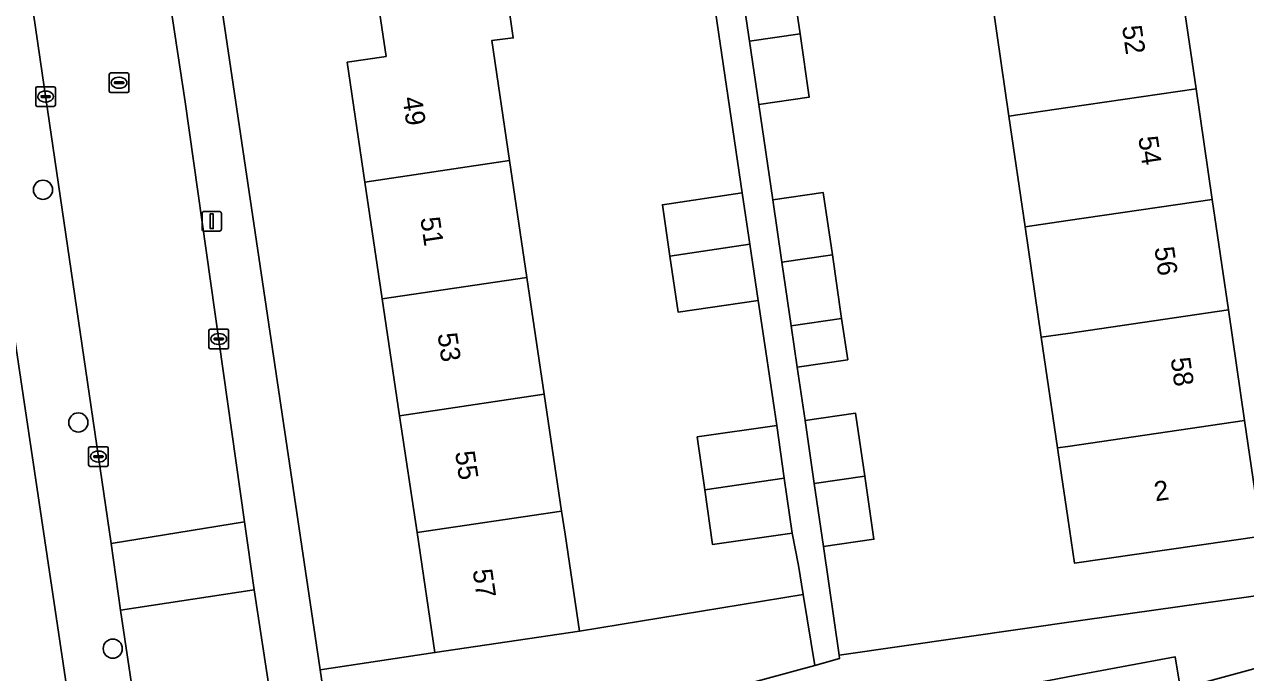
# Model space of a CAD drawing. Extents: x 159053 to 160042, y 380449 to 381423.
# Drawn here: x 159446.8 to 159509.1, y 381000.3 to 381033.4 of the extents above; entities that cross this region are included whole.
import ezdxf

# ---------------------------------------------------------------- set-up
doc = ezdxf.new("R2010")
doc.units = 0
for name, color, linetype in [('IMGEO_Berm_groen', 7, 'Continuous'), ('IMGEO_Boom', 7, 'Continuous'), ('IMGEO_Erf', 7, 'Continuous'), ('IMGEO_Groenvoorziening', 7, 'Continuous'), ('IMGEO_Kolk', 7, 'Continuous'), ('IMGEO_Lichtmast', 7, 'Continuous'), ('IMGEO_Muur', 7, 'Continuous'), ('IMGEO_Pand', 7, 'Continuous'), ('IMGEO_Pand_nummerreeks', 7, 'Continuous'), ('IMGEO_Rijbaan_lokaal_open', 7, 'Continuous'), ('IMGEO_Rioolput', 7, 'Continuous'), ('IMGEO_Voetpad_open', 7, 'Continuous')]:
    doc.layers.add(name, color=color, linetype=linetype)

msp = doc.modelspace()

# ---------------------------------------------------------------- linework, layer by layer
at = {"layer": 'IMGEO_Berm_groen'}
msp.add_lwpolyline([(159505.757, 380999.512), (159505.672, 381000), (159505.48, 381001.138), (159500, 381000.115), (159499.383, 381000), (159491.273, 380998.489), (159490.625, 380998.368), (159491.304, 380995.431), (159492.6, 380995.796), (159495.295, 380996.554), (159500, 380997.877)], close=True, dxfattribs=at)
at = {"layer": 'IMGEO_Boom'}
for centre in [(159447.726, 381024.945), (159449.529, 381013.083), (159451.285, 381001.557)]:
    msp.add_circle(centre, 0.489, dxfattribs=at)
at = {"layer": 'IMGEO_Erf'}
for points in [[(159445.63, 380994.272), (159449.622, 380994.989), (159448.874, 381000), (159435.479, 381089.722)], [(159448.814, 381088.274), (159461.87, 381000.484), (159467.715, 381001.353), (159466.806, 381007.468), (159465.92, 381013.422), (159465.035, 381019.377), (159464.149, 381025.331), (159463.24, 381031.447), (159465.226, 381031.742), (159464.785, 381034.705)], [(159485.874, 381036.1), (159486.343, 381032.898), (159486.815, 381029.671), (159484.239, 381029.297), (159484.955, 381024.427), (159487.527, 381024.804), (159487.992, 381021.623), (159488.466, 381018.384), (159488.774, 381016.282), (159486.201, 381015.905), (159486.601, 381013.18), (159489.173, 381013.556), (159489.642, 381010.35), (159490.112, 381007.136), (159487.54, 381006.76), (159488.332, 381001.222), (159500.763, 381003.012), (159515.381, 381005.067)], [(159471.282, 381035.669), (159471.719, 381032.687), (159470.618, 381032.544), (159471.528, 381026.428), (159472.413, 381020.474), (159473.299, 381014.519), (159474.184, 381008.565), (159474.358, 381007.396), (159475.094, 381002.45), (159486.505, 381004.322), (159486.263, 381005.8), (159485.938, 381007.441), (159481.879, 381006.864), (159481.482, 381009.65), (159481.098, 381012.349), (159485.157, 381012.926), (159484.597, 381016.709), (159484.206, 381019.307), (159480.134, 381018.702), (159479.71, 381021.559), (159479.32, 381024.182), (159483.391, 381024.787), (159482.037, 381034.012)], [(159505.719, 381035.733), (159506.546, 381030.085), (159507.371, 381024.447), (159508.194, 381018.819), (159509.019, 381013.18), (159509.88, 381007.296), (159500.337, 381005.917), (159500, 381008.217), (159499.612, 381010.865), (159499.477, 381011.787), (159498.651, 381017.427), (159497.826, 381023.057), (159496.999, 381028.696), (159496.173, 381034.336)]]:
    msp.add_lwpolyline(points, dxfattribs=at)
at = {"layer": 'IMGEO_Groenvoorziening'}
for points in [[(159487.099, 381000.703), (159486.505, 381004.322), (159475.094, 381002.45), (159467.715, 381001.353), (159461.87, 381000.484), (159462.391, 380996.957)], [(159465.54, 380994.899), (159472.725, 380996.84), (159484.535, 381000), (159487.099, 381000.703)]]:
    msp.add_lwpolyline(points, dxfattribs=at)
at = {"layer": 'IMGEO_Kolk'}
for p, q in [((159447.36, 381029.269), (159447.36, 381030.121)), ((159447.435, 381030.195), (159448.287, 381030.195)), ((159447.619, 381029.689), (159447.619, 381029.701)), ((159448.057, 381029.652), (159447.659, 381029.652)), ((159447.662, 381029.738), (159448.06, 381029.738)), ((159447.848, 381029.975), (159447.873, 381029.975)), ((159448.103, 381029.701), (159448.103, 381029.689)), ((159448.361, 381030.121), (159448.361, 381029.269)), ((159448.287, 381029.195), (159447.435, 381029.195)), ((159447.871, 381029.415), (159447.846, 381029.415)), ((159456.267, 381017.839), (159457.119, 381017.839)), ((159456.192, 381016.913), (159456.192, 381017.765)), ((159456.451, 381017.333), (159456.451, 381017.345)), ((159456.889, 381017.296), (159456.491, 381017.296)), ((159456.494, 381017.382), (159456.892, 381017.382)), ((159456.68, 381017.619), (159456.705, 381017.619)), ((159456.935, 381017.345), (159456.935, 381017.333)), ((159457.193, 381017.765), (159457.193, 381016.913)), ((159457.119, 381016.839), (159456.267, 381016.839)), ((159456.703, 381017.059), (159456.678, 381017.059)), ((159450.055, 381010.92), (159450.055, 381011.772)), ((159450.13, 381011.846), (159450.982, 381011.846)), ((159450.543, 381011.626), (159450.568, 381011.626)), ((159451.056, 381011.772), (159451.056, 381010.92)), ((159450.314, 381011.34), (159450.314, 381011.352)), ((159450.752, 381011.303), (159450.354, 381011.303)), ((159450.357, 381011.389), (159450.755, 381011.389)), ((159450.566, 381011.066), (159450.541, 381011.066)), ((159450.798, 381011.352), (159450.798, 381011.34)), ((159450.982, 381010.846), (159450.13, 381010.846))]:
    msp.add_line(p, q, dxfattribs=at)
for points in [[(159447.36, 381029.269), (159447.36, 381030.121)], [(159447.435, 381030.195), (159448.287, 381030.195)], [(159448.361, 381030.121), (159448.361, 381029.269)], [(159448.287, 381029.195), (159447.435, 381029.195)], [(159456.267, 381017.839), (159457.119, 381017.839)], [(159456.192, 381016.913), (159456.192, 381017.765)], [(159457.193, 381017.765), (159457.193, 381016.913)], [(159457.119, 381016.839), (159456.267, 381016.839)], [(159450.055, 381010.92), (159450.055, 381011.772)], [(159450.13, 381011.846), (159450.982, 381011.846)], [(159451.056, 381011.772), (159451.056, 381010.92)], [(159450.982, 381010.846), (159450.13, 381010.846)]]:
    msp.add_lwpolyline(points, dxfattribs=at)
for centre, radius, start, end in [((159447.437, 381030.119), 0.0765, 91.55205, 178.44795), ((159447.437, 381030.119), 0.0765, 91.55205, 178.44795), ((159447.659, 381029.698), 0.0403, 85.87752, 175.75265), ((159447.656, 381029.688), 0.0366, 178.93798, 274.71019), ((159448.06, 381029.695), 0.043, 264.86636, 352.45326), ((159448.064, 381029.7), 0.0386, 1.73085, 96.63898), ((159448.285, 381030.119), 0.0765, 1.55205, 88.44795), ((159448.285, 381030.119), 0.0765, 1.55205, 88.44795), ((159447.437, 381029.271), 0.0765, 181.55205, 268.44795), ((159447.437, 381029.271), 0.0765, 181.55205, 268.44795), ((159448.285, 381029.271), 0.0765, 271.55205, 358.44795), ((159448.285, 381029.271), 0.0765, 271.55205, 358.44795), ((159456.269, 381017.763), 0.0765, 91.55205, 178.44795), ((159456.269, 381017.763), 0.0765, 91.55205, 178.44795), ((159457.117, 381017.763), 0.0765, 1.55205, 88.44795), ((159457.117, 381017.763), 0.0765, 1.55205, 88.44795), ((159456.491, 381017.342), 0.0403, 85.87752, 175.75265), ((159456.488, 381017.332), 0.0366, 178.93798, 274.71019), ((159456.892, 381017.339), 0.043, 264.86636, 352.45326), ((159456.896, 381017.344), 0.0386, 1.73085, 96.63898), ((159456.269, 381016.915), 0.0765, 181.55205, 268.44795), ((159456.269, 381016.915), 0.0765, 181.55205, 268.44795), ((159457.117, 381016.915), 0.0765, 271.55205, 358.44795), ((159457.117, 381016.915), 0.0765, 271.55205, 358.44795), ((159450.132, 381011.77), 0.0765, 91.55205, 178.44795), ((159450.132, 381011.77), 0.0765, 91.55205, 178.44795), ((159450.98, 381011.77), 0.0765, 1.55205, 88.44795), ((159450.98, 381011.77), 0.0765, 1.55205, 88.44795), ((159450.132, 381010.922), 0.0765, 181.55205, 268.44795), ((159450.132, 381010.922), 0.0765, 181.55205, 268.44795), ((159450.354, 381011.349), 0.0403, 85.87752, 175.75265), ((159450.351, 381011.339), 0.0366, 178.93798, 274.71019), ((159450.755, 381011.346), 0.043, 264.86636, 352.45326), ((159450.759, 381011.351), 0.0386, 1.73085, 96.63898), ((159450.98, 381010.922), 0.0765, 271.55205, 358.44795), ((159450.98, 381010.922), 0.0765, 271.55205, 358.44795)]:
    msp.add_arc(centre, radius, start, end, dxfattribs=at)
for centre, major_axis, ratio, start_param, end_param in [((159447.847, 381029.695), (-0.387, 0.002), 0.722429, 4.712389, 7.853982), ((159447.872, 381029.695), (-0.39, 0.002), 0.717154, 1.570796, 4.712389), ((159456.679, 381017.339), (-0.387, 0.002), 0.722429, 4.712389, 7.853982), ((159456.704, 381017.339), (-0.39, 0.002), 0.717154, 1.570796, 4.712389), ((159450.542, 381011.346), (-0.387, 0.002), 0.722429, 4.712389, 7.853982), ((159450.567, 381011.346), (-0.39, 0.002), 0.717154, 1.570796, 4.712389)]:
    msp.add_ellipse(centre, major_axis=major_axis, ratio=ratio, start_param=start_param, end_param=end_param, dxfattribs=at)
at = {"layer": 'IMGEO_Lichtmast'}
for p, q in [((159455.841, 381022.937), (159455.841, 381023.737)), ((159455.841, 381023.737), (159455.841, 381022.937)), ((159455.941, 381023.837), (159456.731, 381023.837)), ((159456.731, 381023.837), (159455.941, 381023.837)), ((159456.831, 381023.737), (159456.831, 381022.937)), ((159456.831, 381022.937), (159456.831, 381023.737)), ((159456.731, 381022.837), (159455.941, 381022.837)), ((159455.941, 381022.837), (159456.731, 381022.837))]:
    msp.add_line(p, q, dxfattribs=at)
msp.add_lwpolyline([(159456.261, 381023.712), (159456.411, 381023.712), (159456.411, 381022.962), (159456.261, 381022.962), (159456.261, 381023.712)], dxfattribs=at)
for centre, start, end in [((159455.941, 381023.737), 90, 180), ((159455.941, 381023.737), 90, 180), ((159456.731, 381023.737), 0, 90), ((159456.731, 381023.737), 360, 90), ((159455.941, 381022.937), 180, 270), ((159455.941, 381022.937), 180, 270), ((159456.731, 381022.937), 270, 0), ((159456.731, 381022.937), 270, 0)]:
    msp.add_arc(centre, 0.1, start, end, dxfattribs=at)
at = {"layer": 'IMGEO_Muur'}
msp.add_lwpolyline([(159488.332, 381001.222), (159500.763, 381003.012)], dxfattribs=at)
at = {"layer": 'IMGEO_Pand'}
for points in [[(159486.343, 381032.898), (159485.874, 381036.1), (159483.295, 381035.731), (159483.766, 381032.521)], [(159470.618, 381032.544), (159471.719, 381032.687), (159471.282, 381035.669), (159471.238, 381035.662), (159464.785, 381034.705), (159465.226, 381031.742), (159463.24, 381031.447), (159464.149, 381025.331), (159471.528, 381026.428)], [(159505.719, 381035.733), (159500, 381034.896), (159496.173, 381034.336), (159496.999, 381028.696), (159500, 381029.133), (159506.546, 381030.085)], [(159486.343, 381032.898), (159483.766, 381032.521), (159484.239, 381029.297), (159486.815, 381029.671)], [(159506.546, 381030.085), (159500, 381029.133), (159496.999, 381028.696), (159497.826, 381023.057), (159500, 381023.373), (159507.371, 381024.447)], [(159464.149, 381025.331), (159465.035, 381019.377), (159472.413, 381020.474), (159471.528, 381026.428)], [(159483.391, 381024.787), (159479.32, 381024.182), (159479.71, 381021.559), (159483.787, 381022.165)], [(159487.992, 381021.623), (159487.527, 381024.804), (159484.955, 381024.427), (159485.42, 381021.249)], [(159508.194, 381018.819), (159507.371, 381024.447), (159500, 381023.373), (159497.826, 381023.057), (159498.651, 381017.427), (159500, 381017.623)], [(159483.787, 381022.165), (159479.71, 381021.559), (159480.134, 381018.702), (159484.206, 381019.307)], [(159487.992, 381021.623), (159485.42, 381021.249), (159485.894, 381018.007), (159488.466, 381018.384)], [(159473.299, 381014.519), (159472.413, 381020.474), (159465.035, 381019.377), (159465.92, 381013.422)], [(159499.477, 381011.787), (159500, 381011.863), (159509.019, 381013.18), (159508.194, 381018.819), (159500, 381017.623), (159498.651, 381017.427)], [(159488.466, 381018.384), (159485.894, 381018.007), (159486.201, 381015.905), (159488.774, 381016.282)], [(159466.806, 381007.468), (159474.184, 381008.565), (159473.299, 381014.519), (159465.92, 381013.422)], [(159489.642, 381010.35), (159489.173, 381013.556), (159486.601, 381013.18), (159487.07, 381009.975)], [(159481.482, 381009.65), (159485.538, 381010.253), (159485.157, 381012.926), (159481.098, 381012.349)], [(159499.477, 381011.787), (159499.612, 381010.865), (159500, 381008.217), (159500.337, 381005.917), (159509.88, 381007.296), (159509.019, 381013.18), (159500, 381011.863)], [(159489.642, 381010.35), (159487.07, 381009.975), (159487.54, 381006.76), (159490.112, 381007.136)], [(159481.482, 381009.65), (159481.879, 381006.864), (159485.938, 381007.441), (159485.538, 381010.253)], [(159466.806, 381007.468), (159467.715, 381001.353), (159475.094, 381002.45), (159474.358, 381007.396), (159474.184, 381008.565)]]:
    msp.add_lwpolyline(points, close=True, dxfattribs=at)
at = {"layer": 'IMGEO_Rijbaan_lokaal_open'}
for points in [[(159458.014, 381008.022), (159454.981, 381029.422), (159453.929, 381036.365), (159450.806, 381057.803), (159443.858, 381056.823), (159446.657, 381037.89), (159447.686, 381030.883), (159451.207, 381006.916)], [(159458.502, 381004.55), (159458.014, 381008.022), (159451.207, 381006.916), (159451.686, 381003.522)]]:
    msp.add_lwpolyline(points, close=True, dxfattribs=at)
for points in [[(159460.278, 380992.902), (159460.213, 380993.326), (159459.721, 380996.557), (159458.502, 381004.55), (159451.686, 381003.522), (159452.881, 380995.45), (159453.189, 380993.369), (159453.588, 380990.672)], [(159515.537, 381002.185), (159510.493, 381000.794), (159507.56, 381000), (159505.757, 380999.512), (159500, 380997.877), (159495.295, 380996.554), (159496.648, 380991.749), (159500, 380992.678), (159503.747, 380993.717), (159510.54, 380995.6), (159515.081, 380996.86), (159515.643, 380997.016), (159517.099, 380997.4)]]:
    msp.add_lwpolyline(points, dxfattribs=at)
at = {"layer": 'IMGEO_Rioolput'}
for p, q in [((159451.185, 381030.898), (159452.037, 381030.898)), ((159451.11, 381029.972), (159451.11, 381030.824)), ((159451.369, 381030.392), (159451.369, 381030.404)), ((159451.807, 381030.355), (159451.409, 381030.355)), ((159451.412, 381030.441), (159451.81, 381030.441)), ((159451.598, 381030.678), (159451.623, 381030.678)), ((159451.853, 381030.404), (159451.853, 381030.392)), ((159452.111, 381030.824), (159452.111, 381029.972)), ((159452.037, 381029.898), (159451.185, 381029.898)), ((159451.621, 381030.118), (159451.596, 381030.118))]:
    msp.add_line(p, q, dxfattribs=at)
for points in [[(159451.185, 381030.898), (159452.037, 381030.898)], [(159451.11, 381029.972), (159451.11, 381030.824)], [(159452.111, 381030.824), (159452.111, 381029.972)], [(159452.037, 381029.898), (159451.185, 381029.898)]]:
    msp.add_lwpolyline(points, dxfattribs=at)
for centre, radius, start, end in [((159451.187, 381030.822), 0.0765, 91.55205, 178.44795), ((159451.187, 381030.822), 0.0765, 91.55205, 178.44795), ((159452.035, 381030.822), 0.0765, 1.55205, 88.44795), ((159452.035, 381030.822), 0.0765, 1.55205, 88.44795), ((159451.409, 381030.401), 0.0403, 85.87752, 175.75265), ((159451.406, 381030.391), 0.0366, 178.93798, 274.71019), ((159451.81, 381030.398), 0.043, 264.86636, 352.45326), ((159451.814, 381030.403), 0.0386, 1.73085, 96.63898), ((159451.187, 381029.974), 0.0765, 181.55205, 268.44795), ((159451.187, 381029.974), 0.0765, 181.55205, 268.44795), ((159452.035, 381029.974), 0.0765, 271.55205, 358.44795), ((159452.035, 381029.974), 0.0765, 271.55205, 358.44795)]:
    msp.add_arc(centre, radius, start, end, dxfattribs=at)
for centre, major_axis, ratio, start_param, end_param in [((159451.597, 381030.398), (-0.387, 0.002), 0.722429, 4.712389, 7.853982), ((159451.622, 381030.398), (-0.39, 0.002), 0.717154, 1.570796, 4.712389)]:
    msp.add_ellipse(centre, major_axis=major_axis, ratio=ratio, start_param=start_param, end_param=end_param, dxfattribs=at)
at = {"layer": 'IMGEO_Voetpad_open'}
for points in [[(159441.932, 381117.978), (159444.103, 381103.428), (159444.583, 381100.003), (159450.287, 381061.32), (159450.806, 381057.803), (159453.929, 381036.365), (159454.981, 381029.422), (159458.014, 381008.022), (159458.502, 381004.55), (159459.721, 380996.557), (159460.213, 380993.326), (159465.54, 380994.899)], [(159434.725, 381116.398), (159431.519, 381116.656), (159433.919, 381100.289), (159434.916, 381093.497), (159435.479, 381089.722), (159448.874, 381000), (159449.622, 380994.989)], [(159447.686, 381030.883), (159446.657, 381037.89), (159443.858, 381056.823), (159443.344, 381060.378), (159437.701, 381098.967), (159437.198, 381102.422), (159435.439, 381114.494)], [(159462.391, 380996.957), (159461.87, 381000.484), (159448.814, 381088.274)], [(159482.037, 381034.012), (159483.391, 381024.787), (159483.787, 381022.165), (159484.206, 381019.307), (159484.597, 381016.709), (159485.157, 381012.926), (159485.538, 381010.253), (159485.938, 381007.441), (159486.263, 381005.8), (159486.505, 381004.322), (159487.099, 381000.703), (159488.348, 381001.046), (159488.332, 381001.222), (159487.54, 381006.76), (159487.07, 381009.975), (159486.601, 381013.18), (159486.201, 381015.905), (159485.894, 381018.007), (159485.42, 381021.249), (159484.955, 381024.427), (159484.239, 381029.297), (159483.766, 381032.521), (159483.295, 381035.731)], [(159447.546, 380991.822), (159453.189, 380993.369), (159452.881, 380995.45), (159451.686, 381003.522), (159451.207, 381006.916), (159447.686, 381030.883)], [(159491.273, 380998.489), (159499.383, 381000), (159500, 381000.115), (159505.48, 381001.138), (159505.672, 381000), (159505.757, 380999.512), (159507.56, 381000), (159510.493, 381000.794), (159515.537, 381002.185), (159515.381, 381005.067), (159500.763, 381003.012), (159488.332, 381001.222), (159488.348, 381001.046), (159487.099, 381000.703), (159484.535, 381000), (159472.725, 380996.84), (159465.54, 380994.899), (159460.213, 380993.326), (159460.278, 380992.902)]]:
    msp.add_lwpolyline(points, dxfattribs=at)

# ---------------------------------------------------------------- texts
at = {"layer": 'IMGEO_Pand_nummerreeks'}
for s, rotation, p in [('52', 278.32428, (159502.766, 381033.26)), ('49', 278.45665, (159466.059, 381029.626)), ('54', 278.32428, (159503.591, 381027.618)), ('51', 278.45795, (159466.971, 381023.495)), ('56', 278.32428, (159504.416, 381021.98)), ('53', 278.45795, (159467.849, 381017.589)), ('58', 278.32428, (159505.241, 381016.339)), ('55', 278.45795, (159468.744, 381011.57)), ('2', 8.22254, (159504.474, 381009.061)), ('57', 278.45795, (159469.639, 381005.551))]:
    msp.add_text(s, height=1, rotation=rotation, dxfattribs=at).set_placement(p)

doc.saveas('drawing.dxf')
